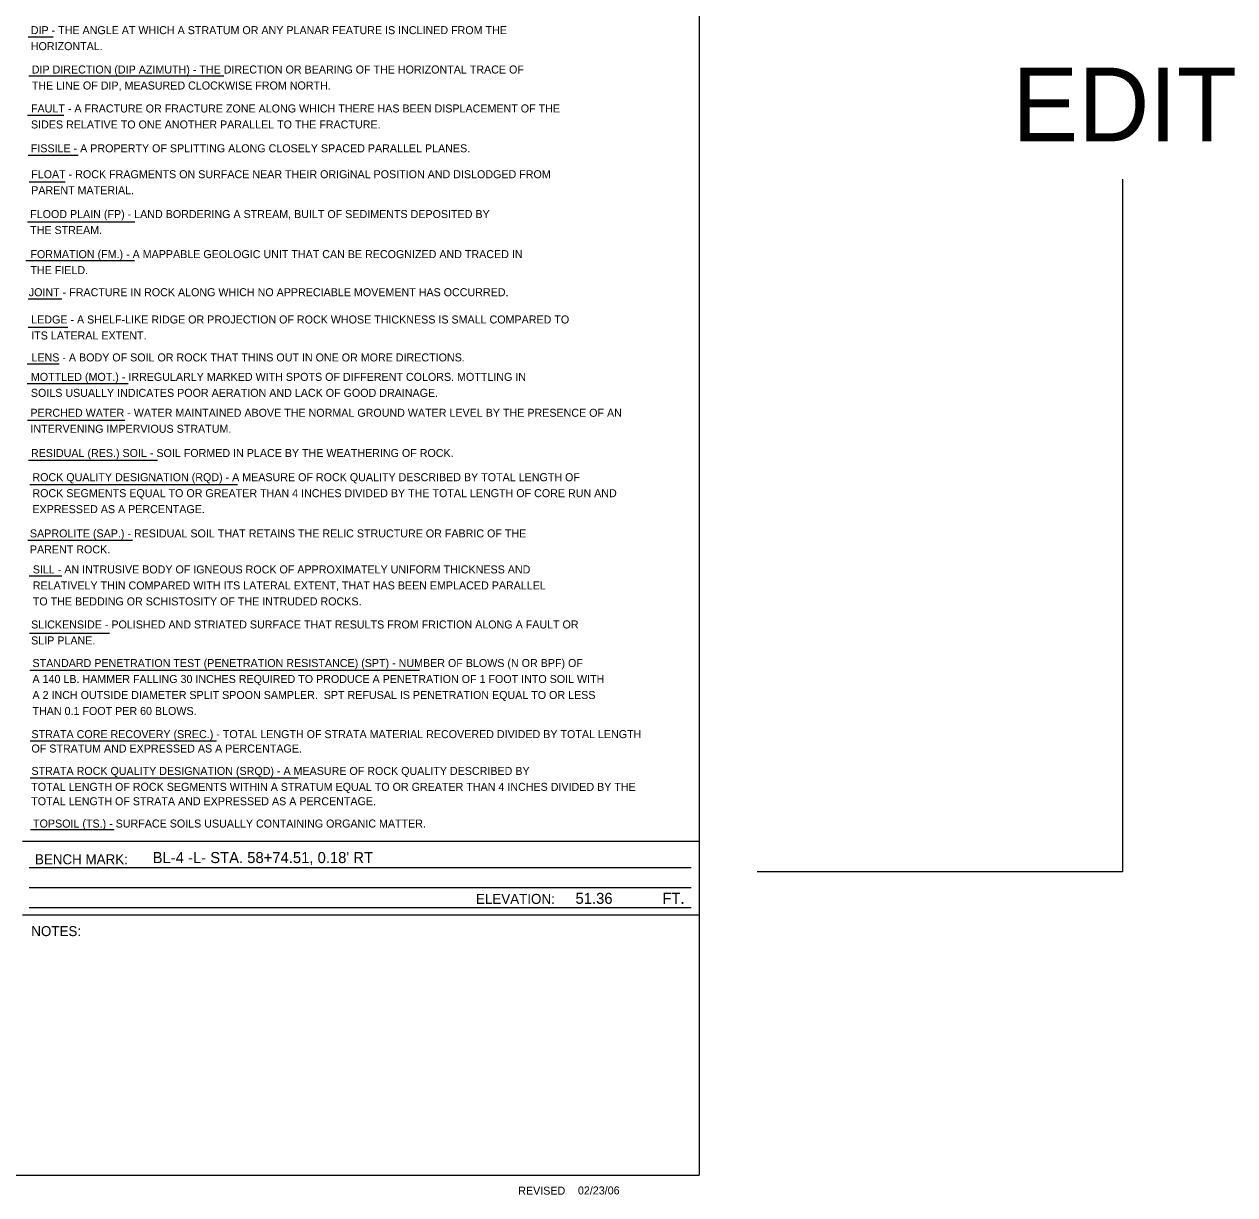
# Model space of a CAD drawing. Extents: x 278710 to 279187, y 171464 to 171625.
# Drawn here: x 279121.4 to 279187.1, y 171484.7 to 171548.2 of the extents above; entities that cross this region are included whole.
import ezdxf

# ---------------------------------------------------------------- set-up
doc = ezdxf.new("R2010")
doc.units = 0
doc.layers.add('Geotech Sheets and Borders Cell', color=7, linetype='Continuous')

msp = doc.modelspace()

# ---------------------------------------------------------------- linework, layer by layer
at = {"layer": 'Geotech Sheets and Borders Cell'}
for p, q in [((279158.027, 171581.203), (279158.027, 171485.806)), ((279158.027, 171566.918), (279158.027, 171485.806)), ((279121.64, 171547.54), (279122.994, 171547.54)), ((279121.679, 171545.41), (279132.238, 171545.41)), ((279121.601, 171543.285), (279123.562, 171543.285)), ((279121.64, 171541.116), (279124.351, 171541.116)), ((279121.684, 171539.667), (279123.644, 171539.667)), ((279121.592, 171537.507), (279127.425, 171537.507)), ((279121.51, 171535.398), (279121.549, 171535.398)), ((279121.549, 171535.398), (279127.397, 171535.398)), ((279121.64, 171533.32), (279123.462, 171533.32)), ((279121.636, 171531.793), (279123.783, 171531.793)), ((279121.588, 171529.807), (279123.319, 171529.807)), ((279121.584, 171528.739), (279127.05, 171528.739)), ((279121.601, 171526.74), (279126.885, 171526.74)), ((279121.649, 171524.584), (279128.643, 171524.584)), ((279121.727, 171523.252), (279132.988, 171523.252)), ((279121.614, 171520.241), (279127.295, 171520.241)), ((279121.684, 171518.307), (279123.458, 171518.307)), ((279121.705, 171515.205), (279126.052, 171515.205)), ((279121.727, 171513.192), (279142.853, 171513.192)), ((279121.749, 171509.357), (279131.843, 171509.357)), ((279121.74, 171507.344), (279136.277, 171507.344)), ((279121.762, 171504.551), (279126.304, 171504.551)), ((279121.332, 171503.922), (279158.027, 171503.922)), ((279121.688, 171502.482), (279157.589, 171502.482)), ((279121.688, 171501.397), (279157.589, 171501.397)), ((279121.332, 171499.931), (279158.027, 171499.931)), ((279121.688, 171500.313), (279157.589, 171500.313)), ((279005.33, 171485.806), (279158.027, 171485.806))]:
    msp.add_line(p, q, dxfattribs=at)
msp.add_lwpolyline([(279180.983, 171539.824), (279180.983, 171502.252), (279161.167, 171502.252)], dxfattribs=at)

# ---------------------------------------------------------------- texts
for s, height, p in [('DIP - THE ANGLE AT WHICH A STRATUM OR ANY PLANAR FEATURE IS INCLINED FROM THE', 0.43381, (279121.779, 171547.679)), ('HORIZONTAL.', 0.43381, (279121.779, 171546.812)), ('DIP DIRECTION (DIP AZIMUTH) - THE DIRECTION OR BEARING OF THE HORIZONTAL TRACE OF ', 0.43381, (279121.831, 171545.545)), ('EDIT', 4, (279175.002, 171541.867)), ('THE LINE OF DIP, MEASURED CLOCKWISE FROM NORTH.', 0.43381, (279121.831, 171544.677)), ('FAULT - A FRACTURE OR FRACTURE ZONE ALONG WHICH THERE HAS BEEN DISPLACEMENT OF THE', 0.43381, (279121.788, 171543.432)), ('SIDES RELATIVE TO ONE ANOTHER PARALLEL TO THE FRACTURE.', 0.43381, (279121.788, 171542.565)), ('FISSILE - A PROPERTY OF SPLITTING ALONG CLOSELY SPACED PARALLEL PLANES.', 0.43381, (279121.779, 171541.272)), ('FLOAT - ROCK FRAGMENTS ON SURFACE NEAR THEIR ORIGiNAL POSITION AND DISLODGED FROM ', 0.43381, (279121.801, 171539.866)), ('PARENT MATERIAL.', 0.43381, (279121.801, 171538.999)), ('FLOOD PLAIN (FP) - LAND BORDERING A STREAM, BUILT OF SEDIMENTS DEPOSITED BY', 0.43381, (279121.744, 171537.706)), ('THE STREAM.', 0.43381, (279121.744, 171536.839)), ('FORMATION (FM.) - A MAPPABLE GEOLOGIC UNIT THAT CAN BE RECOGNIZED AND TRACED IN', 0.43381, (279121.757, 171535.533)), ('THE FIELD.', 0.4338, (279121.757, 171534.665)), ('JOINT - FRACTURE IN ROCK ALONG WHICH NO APPRECIABLE MOVEMENT HAS OCCURRED.', 0.43381, (279121.67, 171533.468)), ('LEDGE - A SHELF-LIKE RIDGE OR PROJECTION OF ROCK WHOSE THICKNESS IS SMALL COMPARED TO ', 0.43381, (279121.801, 171531.989)), ('ITS LATERAL EXTENT.', 0.43381, (279121.801, 171531.121)), ('LENS - A BODY OF SOIL OR ROCK THAT THINS OUT IN ONE OR MORE DIRECTIONS.', 0.43381, (279121.814, 171529.932)), ('MOTTLED (MOT.) - IRREGULARLY MARKED WITH SPOTS OF DIFFERENT COLORS. MOTTLING IN ', 0.43381, (279121.783, 171528.878)), ('SOILS USUALLY INDICATES POOR AERATION AND LACK OF GOOD DRAINAGE.', 0.43381, (279121.783, 171528.011)), ('PERCHED WATER - WATER MAINTAINED ABOVE THE NORMAL GROUND WATER LEVEL BY THE PRESENCE OF AN ', 0.43381, (279121.757, 171526.93)), ('INTERVENING IMPERVIOUS STRATUM.', 0.43381, (279121.757, 171526.063)), ('RESIDUAL (RES.) SOIL - SOIL FORMED IN PLACE BY THE WEATHERING OF ROCK.', 0.43381, (279121.788, 171524.748)), ('ROCK QUALITY DESIGNATION (RQD) - A MEASURE OF ROCK QUALITY DESCRIBED BY TOTAL LENGTH OF ', 0.43381, (279121.866, 171523.438)), ('ROCK SEGMENTS EQUAL TO OR GREATER THAN 4 INCHES DIVIDED BY THE TOTAL LENGTH OF CORE RUN AND ', 0.43381, (279121.866, 171522.571)), ('EXPRESSED AS A PERCENTAGE.', 0.43381, (279121.866, 171521.704)), ('SAPROLITE (SAP.) - RESIDUAL SOIL THAT RETAINS THE RELIC STRUCTURE OR FABRIC OF THE ', 0.43381, (279121.731, 171520.389)), ('PARENT ROCK.', 0.43381, (279121.731, 171519.522)), ('SILL - AN INTRUSIVE BODY OF IGNEOUS ROCK OF APPROXIMATELY UNIFORM THICKNESS AND', 0.43381, (279121.887, 171518.436)), ('RELATIVELY THIN COMPARED WITH ITS LATERAL EXTENT, THAT HAS BEEN EMPLACED PARALLEL', 0.43381, (279121.887, 171517.569)), ('TO THE BEDDING OR SCHISTOSITY OF THE INTRUDED ROCKS.', 0.43381, (279121.887, 171516.702)), ('SLICKENSIDE - POLISHED AND STRIATED SURFACE THAT RESULTS FROM FRICTION ALONG A FAULT OR ', 0.43381, (279121.796, 171515.452)), ('SLIP PLANE.', 0.43381, (279121.796, 171514.585)), ('STANDARD PENETRATION TEST (PENETRATION RESISTANCE) (SPT) - NUMBER OF BLOWS (N OR BPF) OF ', 0.43381, (279121.87, 171513.36)), ('A 140 LB. HAMMER FALLING 30 INCHES REQUIRED TO PRODUCE A PENETRATION OF 1 FOOT INTO SOIL WITH ', 0.43381, (279121.87, 171512.494)), ('A 2 INCH OUTSIDE DIAMETER SPLIT SPOON SAMPLER.  SPT REFUSAL IS PENETRATION EQUAL TO OR LESS', 0.43381, (279121.87, 171511.627)), ('THAN 0.1 FOOT PER 60 BLOWS.', 0.43381, (279121.87, 171510.76)), ('STRATA CORE RECOVERY (SREC.) - TOTAL LENGTH OF STRATA MATERIAL RECOVERED DIVIDED BY TOTAL LENGTH', 0.43381, (279121.814, 171509.505)), ('OF STRATUM AND EXPRESSED AS A PERCENTAGE.', 0.43381, (279121.814, 171508.724)), ('STRATA ROCK QUALITY DESIGNATION (SRQD) - A MEASURE OF ROCK QUALITY DESCRIBED BY', 0.43381, (279121.814, 171507.509)), ('TOTAL LENGTH OF ROCK SEGMENTS WITHIN A STRATUM EQUAL TO OR GREATER THAN 4 INCHES DIVIDED BY THE', 0.43381, (279121.801, 171506.646)), ('TOTAL LENGTH OF STRATA AND EXPRESSED AS A PERCENTAGE.', 0.43381, (279121.801, 171505.865)), ('TOPSOIL (TS.) - SURFACE SOILS USUALLY CONTAINING ORGANIC MATTER.', 0.43381, (279121.9, 171504.655)), ('BENCH MARK:', 0.54224, (279122.005, 171502.664)), ("BL-4 -L- STA. 58+74.51, 0.18' RT", 0.6, (279128.387, 171502.729)), ('51.36', 0.6, (279151.316, 171500.517)), ('FT.', 0.6, (279156.026, 171500.517)), ('ELEVATION:', 0.5422, (279145.92, 171500.516)), ('NOTES:', 0.5422, (279121.805, 171498.768)), ('REVISED ', 0.4338, (279148.21, 171484.748)), ('02/23/06', 0.4338, (279151.447, 171484.761))]:
    msp.add_text(s, height=height, dxfattribs=at).set_placement(p)

doc.saveas('drawing.dxf')
